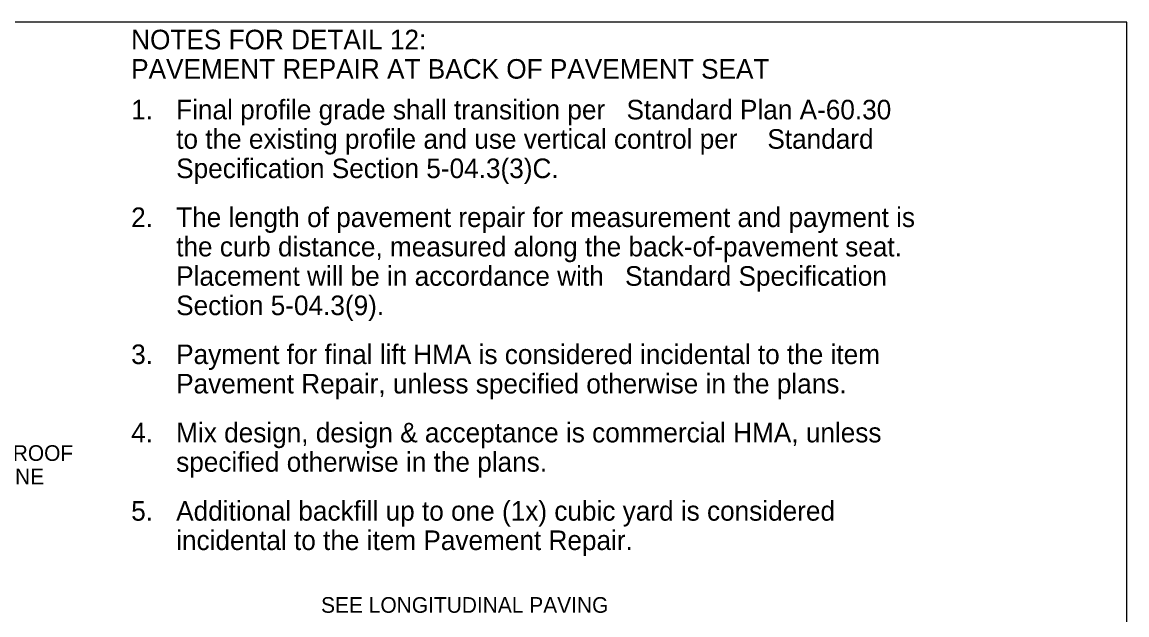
# Model space of a CAD drawing. Extents: x 99862 to 103151, y 100000 to 105076.
# Drawn here: x 102022 to 103151, y 104470 to 105076 of the extents above; entities that cross this region are included whole.
import ezdxf

# ---------------------------------------------------------------- set-up
doc = ezdxf.new("R2010")
doc.units = 0
for name, color, linetype in [('Level 1', 7, 'Continuous'), ('Level 20', 7, 'Continuous'), ('Level 60', 7, 'Continuous')]:
    doc.layers.add(name, color=color, linetype=linetype)

msp = doc.modelspace()

# ---------------------------------------------------------------- linework, layer by layer
at = {"layer": 'Level 1'}
msp.add_lwpolyline([(99862, 102999.5), (103151, 102999.5), (103151, 105075.5), (99862, 105075.5)], close=True, dxfattribs=at)
at = {"layer": 'Level 60'}
msp.add_line((103151, 105075.5), (103151, 105075.5), dxfattribs=at)

# ---------------------------------------------------------------- texts
at = {"layer": 'Level 20'}
for s, height, p in [('NOTES FOR DETAIL 12:', 20, (102133.2, 105047.7)), ('PAVEMENT REPAIR AT BACK OF PAVEMENT SEAT', 20, (102133.2, 105017.7)), ('1.', 20, (102133.2, 104976.1)), ('Final profile grade shall transition per', 20, (102179.2, 104976.1)), (' Standard Plan A-60.30', 20, (102632.1, 104976.1)), ('to the existing profile and use vertical control per ', 20, (102179.2, 104946.1)), ('Standard ', 20, (102783.5, 104946.1)), ('Specification Section 5-04.3(3)C.', 20, (102179.2, 104916.1)), ('2.', 20, (102133.2, 104866.1)), ('The length of pavement repair for measurement and payment is', 20, (102179.2, 104866.1)), ('the curb distance, measured along the back-of-pavement seat.', 20, (102179.2, 104836.1)), ('Placement will be in accordance with', 20, (102179.2, 104806.1)), (' Standard Specification ', 20, (102630.6, 104806.1)), ('Section 5-04.3(9).', 20, (102179.2, 104776.1)), ('3.', 20, (102133.2, 104726.1)), ('Payment for final lift HMA is considered incidental to the item ', 20, (102179.2, 104726.1)), ('Pavement Repair, unless specified otherwise in the plans.', 20, (102179.2, 104696.1)), ('4.', 20, (102133.2, 104646.1)), ('Mix design, design & acceptance is commercial HMA, unless', 20, (102179.2, 104646.1)), ('WATERPROOF ', 16, (101920.6, 104627.2)), ('specified otherwise in the plans.', 20, (102179.2, 104616.1)), ('MEMBRANE', 16, (101920.6, 104603.2)), ('5.', 20, (102133.2, 104566.1)), ('Additional backfill up to one (1x) cubic yard is considered ', 20, (102179.2, 104566.1)), ('incidental to the item Pavement Repair.', 20, (102179.2, 104536.1)), ('SEE LONGITUDINAL PAVING', 16, (102327.3, 104472))]:
    msp.add_text(s, height=height, dxfattribs=at).set_placement(p)

doc.saveas('drawing.dxf')
